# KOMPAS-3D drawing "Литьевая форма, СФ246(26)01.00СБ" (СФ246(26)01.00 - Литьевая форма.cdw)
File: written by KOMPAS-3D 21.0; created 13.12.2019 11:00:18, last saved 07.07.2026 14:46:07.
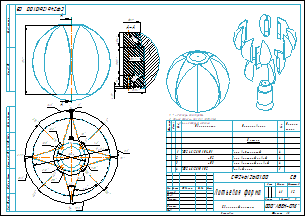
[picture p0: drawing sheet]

Sheet 1: A3, landscape

Document properties: Автор: Воробьев П.С.; Комментарий: Запрещено выносить за территорию производства ООО "Авен-СПб".; Полное имя файла: СФ246(26)01.00 СБ - Литьевая форма.a3d; Масса: 41.005814

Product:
- Part/product: Литьевая форма  | designation СФ246(26)01.00СБ
    Масса: 41.005814
    Комментарий: Запрещается использовать данный документ за пределами ООО "АВЕН-СПб"!
  - Component [detail]: Клин внешний левый  | designation СФ246(26)01.01-02  | qty 4  | pos. 2
      Материал: Ст3сп ГОСТ 380-2005 (density 7850 kg/m3)
      Масса: 2.666764
      Раздел спецификации: Детали
      Параметр неуказанной шероховатости: 12,5
      Знак неуказанной шероховатости: 4
      source file: СФ246(26)01.01 - Внутренняя Сфера.m3d
  - Component [detail]: Клин внутренний  | designation СФ246(26)01.01-01  | qty 4  | pos. 1
      Материал: Ст3сп ГОСТ 380-2005 (density 7850 kg/m3)
      Масса: 1.57996
      Раздел спецификации: Детали
      Параметр неуказанной шероховатости: 12,5
      Знак неуказанной шероховатости: 4
      source file: СФ246(26)01.01 - Внутренняя Сфера.m3d
  - Component [detail]: Клин внешний правый  | designation СФ246(26)01.01-03  | qty 4  | pos. 3
      Материал: Ст3сп ГОСТ 380-2005 (density 7850 kg/m3)
      Масса: 2.671465
      Раздел спецификации: Детали
      Параметр неуказанной шероховатости: 12,5
      Знак неуказанной шероховатости: 4
      source file: СФ246(26)01.01 - Внутренняя Сфера.m3d
  - Component [detail]: Осевой клин  | designation СФ246(26)01.02  | pos. 4
      Материал: Ст3сп ГОСТ 380-2005 (density 7850 kg/m3)
      Масса: 13.333054
      Раздел спецификации: Детали
      Параметр неуказанной шероховатости: 12,5
      Знак неуказанной шероховатости: 4
      source file: СФ246(26)01.02 - Осевой клин.m3d

Title block, sheet 1: Наименование: Литьевая форма; designation: СФ246(26)01.00; Масса: 41; Количество листов документа: 1; organisation: ООО"АВЕН-СПб"; Форматы листов документа: A3; stored path: C:\Program Files\ASCON\KOMPAS-3D v18\Templates\Металл А4в.cdt

Views: Вид 1, Спереди, Проекционный вид 2, Проекционный вид 3, Разрез А-А
Referenced files in E:\заказы\Г-1428(26) - Химоза\3Д\Оснастка\: СФ246(26)01.00 СБ - Литьевая форма.a3d, СФ246(26)01.01 - Внутренняя Сфера.m3d, СФ246(26)01.02 - Осевой клин.m3d
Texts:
  Mipgost
  Версия вида
  Тип вида
  Матрица вида
  Точка разреза
  СФ246(26)01.01 - 02
  СФ246(26)01.01 - 02
  Клин внешний левый
  СФ246(26)01.01-02
  СФ246(26)01.01 - 03
  СФ246(26)01.01 - 03
  Клин внешний правый
  СФ246(26)01.01-03
  СФ246(26)01.01 - 01
  СФ246(26)01.01 - 01
  Клин внутренний
  СФ246(26)01.01-01
  СФ246(26)01.02
  Осевой клин
  ElectricLineNodes
  es-vk-info-doc
  es-ov-info-doc
  es-tx-info-doc
  СФ246(26)01.02 Осевой клин
  СФ246(26)01.01
  СФ246(26)01.01-01 Клин внутренний
  СФ246(26)01.01-02 Клин внешний левый
  СФ246(26)01.01-03 Клин внешний правый
  СФ246(26)01.00 СБ Литьевая форма
Dimensions and other numbers on the sheet: 191; 135; 179; 181; 225; 269; 271; 315; 359; 128; 142; 218; 232; 308; 322; 81; 215,5; 107,5; 4,9; 39; 98,5; 48,6; 115; 4; 2; 3; 1; 1:2; 41; 01; 02; 03

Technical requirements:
  * - Размеры для справок.
  Mipgost
  Общие допуски по ГОСТ 30893.1-m.
  ** - Общий габарит изделия.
